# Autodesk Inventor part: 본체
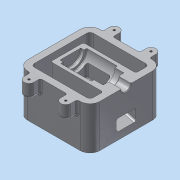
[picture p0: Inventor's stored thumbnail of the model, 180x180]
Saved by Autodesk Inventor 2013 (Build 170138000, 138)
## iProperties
Created: 2018-01
Part Number: 본체
Material: 알루미늄 6061
Document SubType Name: Modeling
Designer: dgall
Density: 2.71 g/cm^3
Mass: 998.337 g
Surface Area: 834.618 cm^2
Volume: 368.39 cm^3
Author: dgall
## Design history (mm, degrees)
sketch "스케치1"
  geometry: L1 (-55, 55)-(55, 55); L2 (55, 55)-(55, -55); L3 (55, -55)-(-55, -55); L4 (-55, -55)-(-55, 55); L5 (45, 45)-(-45, 45); L6 (-45, 45)-(-45, -45); L7 (-45, -45)-(45, -45); L8 (45, -45)-(45, 45); 3 further points
  constraints: 16 end point, 4 parallel, 2 midpoint, 2 perpendicular, 1 horizontal, 1 horizontal alignment, 1 vertical alignment, 3 other
  dimensions: "d0" = 110 distance of L1.start L1.end; "d2" = 110 distance of L1.end L2.end; "d3" = 10 distance between parallel lines of L5 L1
extrude "돌출1" new body sketch "스케치1" distance "d4" = 65; taper "d5" = 0 deg
sketch "스케치2"
  geometry: L1 (55, 55)-(-55, 55) reference; L2 (-55, 55)-(-55, -55) reference; L3 (-35.5, 65)-(-35.5, 55); L4 (-20.5, 65)-(-20.5, 55); L5 (20.5, 65)-(20.5, 55); L6 (35.5, 65)-(35.5, 55); A1 r 7.5 centre (-28, 65) between (-20.5, 65) and (-35.5, 65); A2 r 7.5 centre (28, 65) between (35.5, 65) and (20.5, 65); 1 further point
  constraints: 8 end point, 4 perpendicular, 4 point on circle, 4 point on line, 4 tangent, 2 centre point, 1 equal radius
  dimensions: "d6" = 7.5 radius of A1; "d7" = 10 distance from line of L1 A1.centre; "d8" = 27 distance from line of L2 A1.centre; "d9" = 10 distance from line of L1 A2.centre; "d10" = 56 distance of A2.centre A1.centre
extrude "돌출2" join sketch "스케치2" distance "d11" = 20; taper "d12" = 0 deg
sketch "스케치3"
  geometry: A1 r 7.5 centre (28, 65) between (35.5, 65) and (20.5, 65) reference; A2 r 7.5 centre (-28, 65) between (-20.5, 65) and (-35.5, 65) reference; 3 further points
  constraints: 2 coincident
hole "구멍1" sketch "스케치3" at (-28, 65), (28, 65) diameter "d13" = 3.242; stored, may be unused: countersink angle "d17" = 90 deg, drill point angle "d19" = 118 deg; dims "d14" = 9, "d15" = 4, "d16" = 2, "d18" = 11
fillet "모깎기1" dims "d20" = 15
fillet "모깎기2" dims "d21" = 5
fillet "모깎기3" dims "d22" = 3
sketch "스케치4"
  geometry: L1 (-45, 65)-(-45, 0) reference; L2 (-45, 0)-(-55, 0) reference; L3 (-55, 0)-(-55, 65) reference; L4 (-55, 65)-(-45, 65) reference; L5 (55, 65)-(55, 0) reference; L6 (55, 0)-(45, 0) reference; L7 (45, 0)-(45, 65) reference; L8 (45, 65)-(55, 65) reference; L9 (-45, 8.564)-(35, 30); L10 (40, 0)-(-40, 0) reference; L11 (35, 30)-(35, 65); L12 (35, 65)-(-45, 65); 1 further point
  constraints: 6 end point, 2 perpendicular, 1 point on line
  dimensions: "d23" = 105 deg angle of L9 L1; "d24" = 30 distance from line of L10 L9.end; "d25" = 20 distance between parallel lines of L5 L11
extrude "돌출3" join sketch "스케치4" stored distance "d26" = 50; taper "d27" = 0 deg
sketch "스케치5"
  geometry: L1 (-65, 0)-(-65, 80) reference; C1 r 7.5 at (-65, 40); 1 further point
  constraints: 1 centre point, 1 midpoint
  dimensions: "d28" = 7.5 radius of C1
extrude "돌출4" cut sketch "스케치5" distance "d30" = 85; taper "d31" = 0 deg
sketch "스케치6"
  geometry: C1 r 16 at (-65, 40); A1 r 7.5 centre (-65, 40) between (-65, 32.5) and (-65, 47.5) reference; 1 further point
  constraints: 1 centre point, 1 coincident
  dimensions: "d32" = 16 radius of C1
extrude "돌출5" cut sketch "스케치6" distance "d34" = 66; taper "d35" = 0 deg
node "작업 평면1"
sketch "스케치7"
  geometry: L1 (-27.321, 15)-(-65, 15) reference; L2 (-65, 15)-(-65, 24) reference; L3 (-65, 56)-(-65, 65) reference; L4 (-65, 65)-(-27.321, 65) reference; L5 (-27.321, 65)-(-27.321, 15) reference; L6 (-65, -5)-(0, -5) reference; L7 (0, -5)-(0, -15) reference; L8 (0, -15)-(-42, -15) reference; L9 (-45, -18)-(-45, -28.354) reference; L10 (-48, -31.874)-(-65, -31.874) reference; L11 (-65, -31.874)-(-65, -5) reference; L12 (0, 85)-(-65, 85) reference; L13 (-65, 85)-(-65, 111.874) reference; L14 (-65, 111.874)-(-48, 111.874) reference; L15 (-45, 108.354)-(-45, 98) reference; L16 (-42, 95)-(0, 95) reference; L17 (0, 95)-(0, 85) reference; C1 r 20 at (-65, 40); A1 r 16 centre (-65, 40) between (-65, 24) and (-65, 56) reference; A2 r 3 centre (-42, -18) between (-42, -15) and (-45, -18) reference; A3 r 3 centre (-42, 98) between (-45, 98) and (-42, 95) reference; 1 further point
  constraints: 1 centre point, 1 coincident, 2 other
  dimensions: "d37" = 20 radius of C1
extrude "돌출6" cut sketch "스케치7" distance "d39" = 47; taper "d40" = 0 deg
sketch "스케치8"
  geometry: L1 (35, 65)-(35, 30) reference; L2 (35, 30)-(-45, 8.564) reference; L3 (-45, 8.564)-(-45, 0) reference; L4 (-45, 0)-(-55, 0) reference; L5 (-55, 0)-(-55, 57.5) reference; L6 (-55, 57.5)-(-36, 57.5) reference; L7 (-36, 57.5)-(-36, 49) reference; L8 (-36, 49)-(-22, 49) reference; L9 (-22, 49)-(-22, 45) reference; L10 (-22, 45)-(25, 45) reference; L11 (25, 45)-(25, 49) reference; L12 (25, 49)-(30, 49) reference; L13 (30, 49)-(30, 65) reference; L14 (30, 65)-(35, 65) reference; L15 (55, 65)-(55, 0) reference; L16 (55, 0)-(45, 0) reference; L17 (45, 0)-(45, 65) reference; L18 (45, 65)-(55, 65) reference; L19 (-17, 39.243)-(-55, 29.061); L20 (20, 31.157)-(-55, 11.061); L21 (-17, 39.243)-(-17, 55); L22 (-17, 55)-(20, 55); L23 (20, 55)-(20, 31.157); 1 further point
  constraints: 10 end point, 3 parallel, 2 perpendicular, 2 point on line
  dimensions: "d41" = 5 distance between parallel lines of L2 L20; "d43" = 18 distance of L20.end L19.end; "d45" = 5 distance between parallel lines of L9 L21; "d46" = 37 distance of L21.end L22.end; "d47" = 10 distance between parallel lines of L10 L22
extrude "돌출7" cut sketch "스케치8" stored distance "d48" = 30; taper "d49" = 0 deg
fillet "모깎기4" dims "d50" = 3
fillet "모깎기5" dims "d51" = 3
fillet "모깎기6" dims "d52" = 1
chamfer "모따기1" distance "d53" = 1; stored, may be unused: second distance "d54" = 2, angle "d55" = 45 deg
sketch "스케치9"
  geometry: L1 (0, 0)-(80, 0) reference; L2 (95, -65)-(95, 0) reference; 2 further points
  constraints: 1 other
  dimensions: "d56" = 20 distance from line of L1 point (40, -20); "d57" = 55 distance from line of L2 point (40, -20)
feature "엠보싱1" sketch "스케치9" dims "d0" = 110, "d2" = 110, "d3" = 10, "d6" = 7.5, "d7" = 10, "d8" = 27, "d9" = 10, "d10" = 56, "d58" = 0.5, "d59" = 0
fillet "모깎기7" dims "d60" = 3
fillet "모깎기8" dims "d61" = 3
fillet "모깎기9" dims "d63" = 3
node "솔리드1"
mirror "대칭1"
node "절단 모서리 투영1"
node "절단 모서리 투영2"
node "절단 모서리 투영3"
other parameters: "d36" = 5
